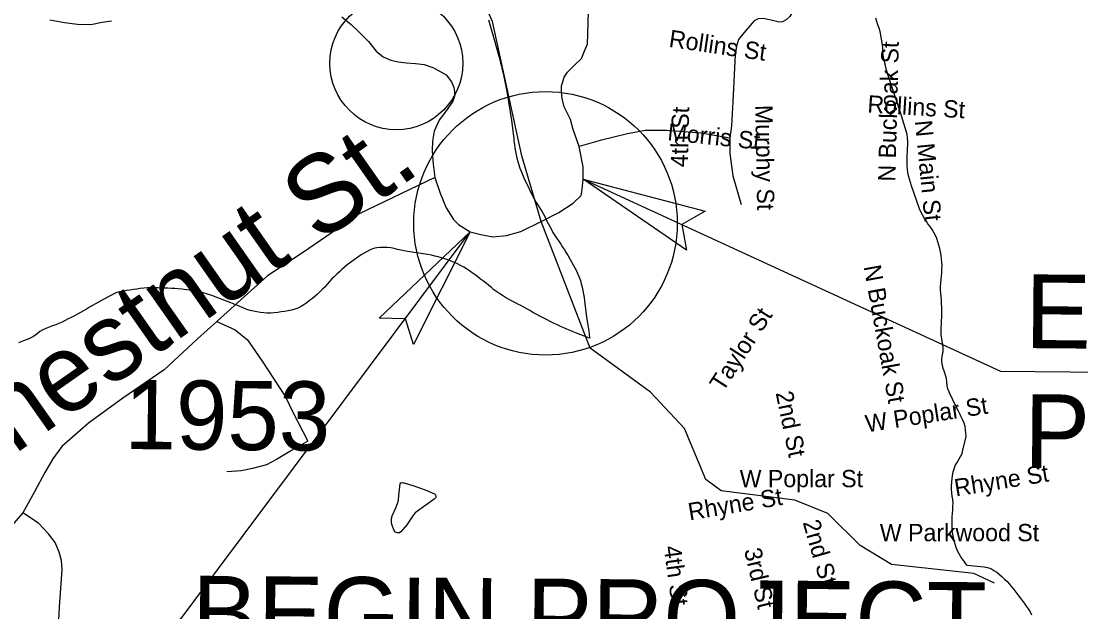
# Model space of a CAD drawing. Extents: x 1379453 to 1387082, y 594364 to 596664.
# Drawn here: x 1380304.5 to 1380505.6, y 596231.5 to 596343.6 of the extents above; entities that cross this region are included whole.
import ezdxf

# ---------------------------------------------------------------- set-up
doc = ezdxf.new("R2010")
doc.units = 0
for name, color, linetype in [('Old_Level_10', 7, 'Continuous'), ('Old_Level_11', 7, 'Continuous'), ('Old_Level_31', 7, 'Continuous'), ('Old_Level_32', 7, 'Continuous'), ('Old_Level_35', 7, 'Continuous'), ('Old_Level_50', 7, 'Continuous'), ('Old_Level_59', 7, 'Continuous'), ('Old_Level_62', 7, 'Continuous'), ('Old_Level_8', 7, 'Continuous'), ('Pattern 1', 7, 'Continuous'), ('Typical Terminator CELL', 7, 'Continuous')]:
    doc.layers.add(name, color=color, linetype=linetype)

msp = doc.modelspace()

# ---------------------------------------------------------------- linework, layer by layer
at = {"layer": 'Old_Level_11'}
for p, q in [((1380411.12, 596313.57), (1380490.3, 596277.16)), ((1380328.61, 596221.97), (1380389.69, 596303.59)), ((1380490.3, 596277.16), (1380585.59, 596276.36))]:
    msp.add_line(p, q, dxfattribs=at)
at = {"layer": 'Old_Level_31'}
msp.add_line((1380405.25, 596305.61), (1380405.25, 596305.61), dxfattribs=at)
at = {"layer": 'Old_Level_32'}
for points in [[(1380441.94, 596375.52), (1380443.8, 596372.99), (1380448.86, 596365.59), (1380454.55, 596357.52), (1380455.22, 596356.35), (1380455.53, 596355.28), (1380455.46, 596354.37), (1380455.19, 596353.05), (1380454.18, 596351.23), (1380452.38, 596347.94), (1380450.36, 596344.46), (1380449.62, 596343.81), (1380448.94, 596343.46), (1380448.31, 596343.41), (1380446.8, 596343.78), (1380445.28, 596344.1), (1380444.34, 596344), (1380443.55, 596343.65), (1380441.68, 596341.42)], [(1380309.92, 596343.86), (1380312.69, 596343.33), (1380315.19, 596343.05), (1380317.71, 596342.98), (1380319.86, 596343.37), (1380321.64, 596343.66)], [(1380365.33, 596344.41), (1380367.1, 596342.97), (1380368.55, 596341.54), (1380370.37, 596339.75), (1380371.82, 596337.91), (1380373.17, 596336.83), (1380374.63, 596336.16), (1380376.04, 596335.84), (1380377.61, 596335.68), (1380379.28, 596335.56), (1380380.95, 596335.35), (1380382.62, 596334.77), (1380384.14, 596334), (1380385.13, 596333.38), (1380386.11, 596332.1), (1380386.57, 596330.98), (1380386.72, 596330.22), (1380386.71, 596329.36), (1380386.39, 596328.39), (1380385.44, 596326.98), (1380383.79, 596324.81), (1380382.84, 596322.74), (1380382.51, 596320.81), (1380382.44, 596318.98), (1380382.63, 596316.45), (1380382.97, 596313.9)], [(1380410.39, 596319.77), (1380409.25, 596323.01), (1380408.74, 596324.93), (1380407.52, 596327.35), (1380407.11, 596328.88), (1380407.02, 596330.2), (1380407.03, 596331.32), (1380407.25, 596332.08), (1380407.51, 596332.94), (1380408.15, 596333.9), (1380409.42, 596335.16), (1380410.79, 596336.52), (1380411.43, 596338.08), (1380411.96, 596339.25), (1380412.05, 596343.21), (1380412.12, 596345.54)], [(1380441.68, 596341.42), (1380440.59, 596340.12), (1380440.21, 596338.86), (1380439.94, 596337.24), (1380439.55, 596328.3), (1380439.25, 596323.74), (1380438.92, 596321.35), (1380433.49, 596322.3), (1380427.02, 596322.81), (1380422.86, 596322.85), (1380419.56, 596322.23), (1380414.32, 596320.94), (1380410.39, 596319.77)], [(1380403.14, 596305.55), (1380406.51, 596307.26), (1380409.25, 596309.06), (1380410.73, 596310.47), (1380410.9, 596311.64), (1380411.12, 596313.57), (1380411.14, 596315.95), (1380410.39, 596319.77)], [(1380382.97, 596313.9), (1380368.47, 596306.97), (1380362.47, 596302.8), (1380357.89, 596299.59), (1380351.2, 596295.24), (1380346.85, 596291.3), (1380341.62, 596286.6)], [(1380382.97, 596313.9), (1380384, 596310.93), (1380385.13, 596308.18), (1380386.52, 596305.95), (1380387.45, 596304.98), (1380389.69, 596303.59), (1380391.72, 596303.07), (1380393.97, 596302.64), (1380396.59, 596302.93), (1380399.32, 596303.66), (1380403.14, 596305.55)], [(1380341.62, 596286.6), (1380337.93, 596283.31), (1380331.6, 596277.42), (1380323.78, 596272.02), (1380317.23, 596267.29), (1380312.22, 596262.86), (1380310.48, 596260.49), (1380308.99, 596257.92), (1380307.03, 596254.23), (1380304.79, 596250.29)], [(1380341.62, 596286.6), (1380345.06, 596285.03), (1380347.45, 596283.13), (1380350.34, 596278.89), (1380354.63, 596272.31), (1380356.02, 596269.35), (1380358.85, 596263.9)], [(1380304.79, 596250.29), (1380301.41, 596246.4), (1380298.84, 596244.9), (1380291, 596240.23), (1380284.25, 596236.51), (1380282.6, 596235.67), (1380280.03, 596234.79), (1380273.2, 596234.03), (1380267.91, 596233.86), (1380249.74, 596234)], [(1380324.65, 596153.76), (1380320.77, 596160.35), (1380309.47, 596179.5), (1380307.8, 596183.75), (1380307.04, 596186.75), (1380306.64, 596190.16), (1380306.89, 596194.27), (1380309.6, 596205.37), (1380311.17, 596215.39), (1380311.25, 596222.21), (1380311.76, 596232.36), (1380312.24, 596239.51), (1380312.15, 596241.19), (1380311.69, 596242.81), (1380310.92, 596244.65), (1380309.68, 596246.28), (1380307.76, 596248.28), (1380304.79, 596250.29)]]:
    msp.add_lwpolyline(points, dxfattribs=at)
msp.add_circle((1380375.67, 596335.59), 12.61, dxfattribs=at)
at = {"layer": 'Old_Level_35'}
for points in [[(1380438.92, 596321.35), (1380438.98, 596318.46), (1380439.49, 596314.2), (1380441.1, 596308.79)], [(1380358.85, 596263.9), (1380355.75, 596262.09), (1380352.91, 596260.39), (1380351.02, 596259.39), (1380348.39, 596258.7), (1380346.2, 596258.21), (1380343.47, 596258.03)]]:
    msp.add_lwpolyline(points, dxfattribs=at)
at = {"layer": 'Old_Level_50'}
msp.add_line((1380403.19, 596305.54), (1380403.19, 596305.54), dxfattribs=at)
at = {"layer": 'Old_Level_59'}
msp.add_lwpolyline([(1380489.17, 596236.91), (1380485.22, 596238.73), (1380469.6, 596240.49), (1380463.7, 596244.08), (1380457.52, 596250.16), (1380451.3, 596252.7), (1380437.31, 596254.42), (1380434.37, 596256.6), (1380430.33, 596266.3), (1380423.87, 596273.18), (1380412.42, 596281.52), (1380403.14, 596305.55), (1380399.48, 596318), (1380393.89, 596343.51), (1380382.94, 596367.85), (1380383.23, 596378.09), (1380384.65, 596381.46), (1380395.92, 596390.07), (1380396.05, 596395.45), (1380392.66, 596401.71)], dxfattribs=at)
at = {"layer": 'Old_Level_62'}
for points in [[(1380474.92, 596307.98), (1380473.42, 596312.32), (1380473.22, 596312.94), (1380473.04, 596313.58), (1380472.88, 596314.22), (1380472.74, 596314.86), (1380472.64, 596315.51), (1380472.59, 596316.16), (1380472.57, 596316.81), (1380472.58, 596317.47), (1380472.61, 596318.13), (1380472.65, 596318.79), (1380472.68, 596319.46), (1380472.71, 596320.11), (1380472.7, 596320.77), (1380472.66, 596321.42), (1380472.58, 596322.06), (1380472.43, 596322.7), (1380472.24, 596323.32), (1380471.28, 596326.47), (1380470.65, 596328.32), (1380469.01, 596333.3), (1380468.81, 596333.93), (1380468.64, 596334.57), (1380468.48, 596335.2), (1380468.33, 596335.84), (1380468.2, 596336.48), (1380468.07, 596337.13), (1380467.99, 596337.78), (1380467.98, 596338.44), (1380467.9, 596339.09), (1380467.48, 596341.65), (1380467.27, 596342.27), (1380467.04, 596342.89), (1380466.83, 596343.52), (1380466.67, 596344.15)], [(1380393.14, 596343.84), (1380394.21, 596340.08), (1380395.1, 596336.92), (1380395.28, 596336.29), (1380395.45, 596335.65), (1380395.61, 596335.02), (1380395.76, 596334.38), (1380395.91, 596333.74), (1380396.05, 596333.1), (1380396.19, 596332.46), (1380396.33, 596331.81), (1380396.46, 596331.17), (1380396.59, 596330.53), (1380396.71, 596329.88), (1380397.54, 596324.72), (1380397.8, 596322.79), (1380397.86, 596322.13), (1380397.93, 596321.47), (1380397.99, 596320.82), (1380398.08, 596320.17), (1380398.16, 596319.52), (1380398.27, 596318.87), (1380398.39, 596318.23), (1380398.53, 596317.59), (1380398.7, 596316.95), (1380398.89, 596316.32), (1380399.1, 596315.7), (1380399.34, 596315.09), (1380399.59, 596314.49), (1380399.86, 596313.88), (1380400.14, 596313.29), (1380400.42, 596312.7), (1380401.28, 596310.92), (1380401.58, 596310.34), (1380401.9, 596309.76), (1380402.22, 596309.19), (1380402.56, 596308.63), (1380402.92, 596308.08), (1380403.27, 596307.52), (1380403.59, 596306.95), (1380403.9, 596306.37), (1380404.19, 596305.78), (1380404.49, 596305.2), (1380404.78, 596304.61), (1380405.08, 596304.03), (1380405.39, 596303.45), (1380405.73, 596302.89), (1380406.12, 596302.36), (1380406.5, 596301.83), (1380406.86, 596301.27), (1380407.21, 596300.72), (1380407.56, 596300.16), (1380407.91, 596299.61), (1380408.25, 596299.05), (1380408.59, 596298.48), (1380408.92, 596297.91), (1380409.24, 596297.34), (1380409.55, 596296.76), (1380409.85, 596296.17), (1380410.12, 596295.58), (1380410.38, 596294.97), (1380410.59, 596294.35), (1380410.76, 596293.72), (1380410.92, 596293.09), (1380411.05, 596292.44), (1380411.17, 596291.79), (1380411.29, 596291.14), (1380411.4, 596290.5), (1380411.7, 596287.94), (1380411.89, 596286.66), (1380412.2, 596284.76), (1380412.25, 596284.11), (1380412.29, 596283.42)], [(1380483.95, 596240.34), (1380483.17, 596241.4), (1380482.8, 596241.94), (1380482.46, 596242.5), (1380482.15, 596243.08), (1380481.9, 596243.69), (1380481.71, 596244.32), (1380481.53, 596244.95), (1380481.37, 596245.59), (1380481.24, 596246.24), (1380481.15, 596246.89), (1380481.11, 596247.54), (1380481.11, 596248.19), (1380481.13, 596248.85), (1380481.17, 596249.5), (1380481.21, 596250.16), (1380481.26, 596250.82), (1380481.29, 596251.48), (1380481.3, 596252.13), (1380481.27, 596252.79), (1380481.17, 596253.44), (1380481.08, 596254.09), (1380481.01, 596254.74), (1380481.02, 596255.4), (1380481.06, 596256.06), (1380481.12, 596256.72), (1380481.22, 596257.37), (1380481.34, 596258.02), (1380481.51, 596258.65), (1380481.74, 596259.25), (1380482.06, 596259.83), (1380482.4, 596260.4), (1380482.73, 596260.97), (1380483.02, 596261.56), (1380483.19, 596262.19), (1380483.79, 596264.73), (1380483.69, 596266), (1380483.59, 596266.66), (1380483.4, 596267.29), (1380483.14, 596267.88), (1380482.86, 596268.48), (1380482.57, 596269.07), (1380482.28, 596269.66), (1380481.99, 596270.25), (1380481.7, 596270.84), (1380481.41, 596271.43), (1380481.12, 596272.02), (1380480.85, 596272.62), (1380480.58, 596273.22), (1380480.33, 596273.82), (1380480.19, 596274.45), (1380480.13, 596275.12), (1380480.05, 596275.77), (1380479.88, 596276.41), (1380479.67, 596277.04), (1380479.46, 596277.67), (1380479.28, 596278.29), (1380479.17, 596278.94), (1380479.18, 596279.58), (1380479.29, 596280.23), (1380479.4, 596280.89), (1380479.46, 596281.54), (1380479.38, 596282.19), (1380479.23, 596282.83), (1380479.06, 596284.12), (1380479.04, 596284.76), (1380479.06, 596285.42), (1380479.09, 596286.08), (1380479.12, 596286.74), (1380479.15, 596287.39), (1380479.17, 596288.05), (1380479.2, 596288.7), (1380479.1, 596290.64), (1380478.97, 596291.93), (1380478.94, 596292.59), (1380478.94, 596293.25), (1380478.97, 596293.9), (1380479.03, 596294.56), (1380479.09, 596295.21), (1380479.16, 596295.87), (1380479.2, 596296.52), (1380479.22, 596297.18), (1380479.19, 596297.83), (1380479.13, 596298.48), (1380479.03, 596299.14), (1380478.91, 596299.79), (1380478.77, 596300.43), (1380478.62, 596301.07), (1380478.44, 596301.7), (1380478.23, 596302.33), (1380477.97, 596302.93), (1380477.67, 596303.5), (1380477.32, 596304.05), (1380476.94, 596304.59), (1380476.55, 596305.13), (1380476.19, 596305.68), (1380475.85, 596306.24), (1380475.51, 596306.81), (1380475.19, 596307.38), (1380474.92, 596307.98)], [(1380412.29, 596283.42), (1380409.85, 596284.39), (1380409.24, 596284.63), (1380408.63, 596284.87), (1380408.02, 596285.12), (1380407.42, 596285.38), (1380406.82, 596285.64), (1380406.22, 596285.92), (1380405.64, 596286.21), (1380401.55, 596288.28), (1380401, 596288.64), (1380400.43, 596288.97), (1380399.86, 596289.28), (1380399.28, 596289.59), (1380398.7, 596289.9), (1380398.12, 596290.21), (1380397.54, 596290.52), (1380396.97, 596290.83), (1380396.39, 596291.16), (1380395.83, 596291.49), (1380395.28, 596291.85), (1380394.73, 596292.21), (1380394.19, 596292.59), (1380393.74, 596293.03), (1380393.22, 596293.43), (1380392.71, 596293.83), (1380392.18, 596294.23), (1380391.66, 596294.63), (1380391.14, 596295.03), (1380390.61, 596295.42), (1380390.08, 596295.81), (1380389.54, 596296.19), (1380389, 596296.56), (1380388.45, 596296.91), (1380387.87, 596297.22), (1380387.28, 596297.51), (1380386.69, 596297.8), (1380386.09, 596298.06), (1380385.46, 596298.26), (1380384.84, 596298.46), (1380384.21, 596298.65), (1380383.58, 596298.84), (1380382.94, 596299.01), (1380382.31, 596299.18), (1380381.67, 596299.33), (1380377.79, 596299.84), (1380375.86, 596300.24), (1380375.23, 596300.42), (1380374.59, 596300.55), (1380373.94, 596300.61), (1380373.27, 596300.64), (1380372.61, 596300.63), (1380371.95, 596300.56), (1380371.31, 596300.42), (1380370.71, 596300.2), (1380370.12, 596299.9), (1380369.54, 596299.57), (1380368.97, 596299.23), (1380366.34, 596297.33), (1380365.83, 596296.91), (1380365.34, 596296.47), (1380364.86, 596296.03), (1380364.38, 596295.57), (1380363.91, 596295.11), (1380363.45, 596294.65), (1380363, 596294.17), (1380362.56, 596293.68), (1380362.13, 596293.19), (1380361.68, 596292.71), (1380361.21, 596292.25), (1380360.73, 596291.8), (1380360.24, 596291.37), (1380359.73, 596290.95), (1380359.21, 596290.55), (1380358.68, 596290.15), (1380358.14, 596289.77), (1380357.58, 596289.42), (1380356.99, 596289.14), (1380356.39, 596288.92), (1380355.75, 596288.75), (1380355.11, 596288.62), (1380354.45, 596288.51), (1380353.8, 596288.4), (1380353.15, 596288.3), (1380352.49, 596288.22), (1380351.84, 596288.17), (1380351.18, 596288.17), (1380350.53, 596288.22), (1380349.88, 596288.3), (1380349.22, 596288.41), (1380348.58, 596288.53), (1380347.94, 596288.68), (1380347.31, 596288.85), (1380346.72, 596289.14), (1380345.51, 596289.65), (1380344.29, 596290.12), (1380340.65, 596291.51), (1380338.16, 596292.27), (1380334.94, 596292.72), (1380334.29, 596292.79)], [(1380334.29, 596292.79), (1380333.63, 596292.83), (1380332.98, 596292.86), (1380332.33, 596292.89), (1380331.67, 596292.91), (1380331.01, 596292.93), (1380330.36, 596292.95), (1380329.7, 596292.96), (1380329.04, 596292.97), (1380328.39, 596292.95), (1380327.73, 596292.9), (1380327.08, 596292.83), (1380326.42, 596292.74), (1380325.77, 596292.65), (1380325.12, 596292.55), (1380324.47, 596292.44), (1380323.82, 596292.33), (1380323.18, 596292.21), (1380322.54, 596292.09), (1380320.3, 596290.87), (1380319.73, 596290.56), (1380319.15, 596290.24), (1380318.57, 596289.92), (1380318, 596289.6), (1380317.43, 596289.28), (1380316.86, 596288.95), (1380316.28, 596288.63), (1380315.71, 596288.31), (1380315.14, 596287.99), (1380314.57, 596287.68), (1380313.99, 596287.36), (1380313.41, 596287.06), (1380312.82, 596286.75), (1380312.24, 596286.46), (1380311.65, 596286.18), (1380311.03, 596285.94), (1380310.41, 596285.73), (1380309.78, 596285.51), (1380309.17, 596285.28), (1380308.58, 596285.01), (1380308.03, 596284.66), (1380307.51, 596284.26), (1380306.98, 596283.86), (1380306.41, 596283.54), (1380305.81, 596283.26), (1380305.2, 596283.01), (1380304.58, 596282.78), (1380303.97, 596282.56)], [(1380377.17, 596255.93), (1380378.96, 596255.38), (1380381.13, 596254.61), (1380382.92, 596253.87), (1380383.1, 596253.67), (1380383.19, 596253.43), (1380383.15, 596253.19), (1380382.84, 596252.86), (1380381.25, 596251.73), (1380379.94, 596250.76), (1380379.26, 596250.25), (1380378.9, 596249.88), (1380378.52, 596249.34), (1380377.65, 596247.99), (1380376.54, 596246.67), (1380376.24, 596246.5), (1380375.85, 596246.5), (1380375.53, 596246.6), (1380375.27, 596246.91), (1380374.82, 596248.03), (1380374.75, 596248.51), (1380374.73, 596249.08), (1380374.86, 596249.69), (1380375.54, 596251.22), (1380375.87, 596252.02), (1380376.05, 596252.7), (1380376.17, 596253.59), (1380376.38, 596255.8), (1380376.44, 596255.97), (1380376.63, 596256.01), (1380376.89, 596255.99), (1380377.17, 596255.93)], [(1380483.95, 596240.34), (1380484.6, 596240.27), (1380485.26, 596240.21), (1380485.91, 596240.15), (1380486.57, 596240.08), (1380487.22, 596240), (1380487.86, 596239.88), (1380488.48, 596239.67), (1380489.06, 596239.35)], [(1380489.06, 596239.35), (1380489.59, 596238.98), (1380490.11, 596238.57), (1380490.61, 596238.13), (1380491.09, 596237.69), (1380491.55, 596237.23), (1380492, 596236.74), (1380492.43, 596236.24), (1380492.83, 596235.72), (1380493.23, 596235.2), (1380493.63, 596234.68), (1380494.02, 596234.16), (1380494.42, 596233.63), (1380494.81, 596233.1), (1380495.2, 596232.57), (1380495.58, 596232.04), (1380495.95, 596231.5), (1380496.22, 596230.9)]]:
    msp.add_lwpolyline(points, dxfattribs=at)
at = {"layer": 'Pattern 1'}
msp.add_circle((1380403.98, 596305.21), 25, dxfattribs=at)
at = {"layer": 'Typical Terminator CELL'}
for points in [[(1380430.73, 596300.11), (1380411.12, 596313.57), (1380434.27, 596307.51), (1380429.81, 596304.97)], [(1380372.43, 596287.23), (1380389.69, 596303.59), (1380378.93, 596282.22), (1380377.38, 596287.11)]]:
    msp.add_lwpolyline(points, close=True, dxfattribs=at)

# ---------------------------------------------------------------- texts
at = {"layer": 'Old_Level_10'}
for s, height, rotation, p in [('Rollins St', 3.281, 351.6748, (1380427.25, 596338.73)), ('N Buckoak St', 3.2808, 88.5592, (1380470.35, 596313.11)), ('Rollins St', 3.281, 356.4874, (1380464.99, 596326.27)), ('4th St', 3.281, 88.7774, (1380431, 596315.83)), ('Murphy St', 3.281, 271.0867, (1380443.76, 596327.66)), ('Morris St', 3.281, 354.1195, (1380427.02, 596320.99)), ('N Main St', 3.281, 275.5388, (1380474.06, 596324.65)), ('N Buckoak St', 3.2808, 280.2638, (1380464.32, 596297.02)), ('Taylor St', 3.281, 57.2006, (1380437.65, 596273.07)), ('2nd St', 3.281, 281.6053, (1380447.63, 596273.04)), ('W Poplar St', 3.2808, 8.8463, (1380464.94, 596265.53)), ('Rhyne St', 3.281, 9.2308, (1380481.83, 596253.36)), ('Rhyne St', 3.281, 9.5179, (1380431.32, 596248.82)), ('2nd St', 3.281, 286.0573, (1380452.76, 596248.46)), ('4th St', 3.281, 277.6187, (1380426.4, 596243.83)), ('3rd St', 3.281, 283.2597, (1380441.63, 596243.2))]:
    msp.add_text(s, height=height, rotation=rotation, dxfattribs=at).set_placement(p)
for s, p in [('W Poplar St', (1380440.82, 596255.13)), ('W Parkwood St', (1380467.41, 596244.88))]:
    msp.add_text(s, height=3.2808, dxfattribs=at).set_placement(p)
at = {"layer": 'Old_Level_11'}
for s, height, rotation, p in [('St.', 14.764, 35.0359, (1380360.88, 596301.26)), ('Chestnut', 14.764, 35.0359, (1380291.43, 596253.04)), ('END', 14, 359.52, (1380494.94, 596281.54)), ('PROJECT', 14, 359.52, (1380494.75, 596258.79)), ('BEGIN PROJECT', 14, 359.52, (1380336.82, 596224.34))]:
    msp.add_text(s, height=height, rotation=rotation, dxfattribs=at).set_placement(p)
at = {"layer": 'Old_Level_8'}
msp.add_text('1953', height=13.123, rotation=359.52, dxfattribs=at).set_placement((1380324.04, 596262.38))

doc.saveas('drawing.dxf')
